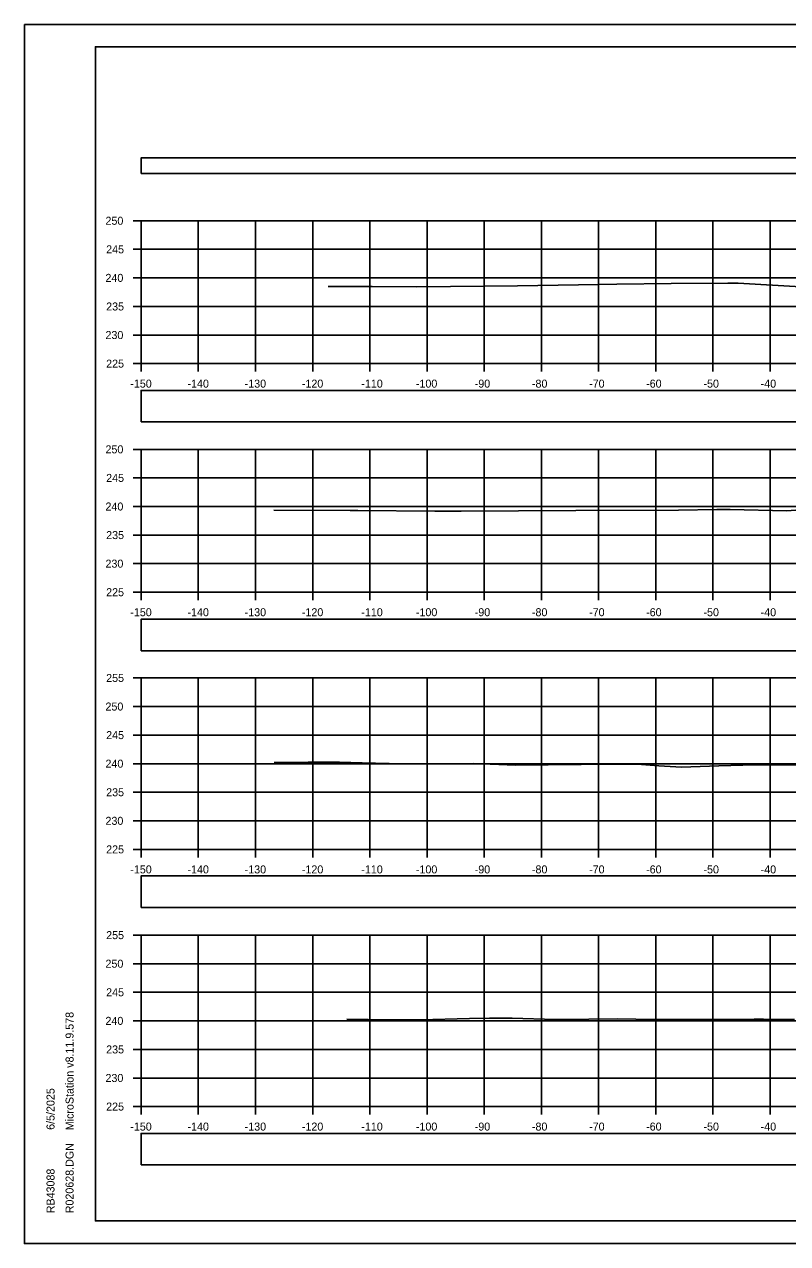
# Model space of a CAD drawing. Extents: x 1369627 to 1374022, y 380035 to 398173.
# Drawn here: x 1370008.8 to 1370142.3, y 380248.2 to 380461.5 of the extents above; entities that cross this region are included whole.
import ezdxf

# ---------------------------------------------------------------- set-up
doc = ezdxf.new("R2010")
doc.units = 0
for name, color, linetype in [('Default', 7, 'Continuous'), ('R_Axis', 7, 'Continuous'), ('R_Axis Annot', 7, 'Continuous'), ('R_Border', 7, 'Continuous'), ('R_Exist Surface', 7, 'Continuous'), ('R_Grid', 7, 'Continuous'), ('R_No Plot', 7, 'Continuous')]:
    doc.layers.add(name, color=color, linetype=linetype)

msp = doc.modelspace()

# ---------------------------------------------------------------- linework, layer by layer
at = {"layer": 'Default'}
for points in [[(1370029.24, 380435.47), (1370329.24, 380435.47), (1370329.24, 380438.18), (1370029.24, 380438.18)], [(1370029.24, 380391.98), (1370329.24, 380391.98), (1370329.24, 380397.5), (1370029.24, 380397.5)], [(1370029.24, 380351.95), (1370329.24, 380351.95), (1370329.24, 380357.47), (1370029.24, 380357.47)], [(1370029.24, 380307.01), (1370329.24, 380307.01), (1370329.24, 380312.54), (1370029.24, 380312.54)], [(1370029.24, 380261.98), (1370329.24, 380261.98), (1370329.24, 380267.5), (1370029.24, 380267.5)]]:
    msp.add_lwpolyline(points, close=True, dxfattribs=at)
at = {"layer": 'R_Axis'}
for p, q in [((1370027.84, 380427.19), (1370029.24, 380427.19)), ((1370029.24, 380402.19), (1370029.24, 380427.19)), ((1370027.84, 380422.19), (1370029.24, 380422.19)), ((1370027.84, 380417.19), (1370029.24, 380417.19)), ((1370027.84, 380412.19), (1370029.24, 380412.19)), ((1370027.84, 380407.19), (1370029.24, 380407.19)), ((1370027.84, 380402.19), (1370029.24, 380402.19)), ((1370029.24, 380402.19), (1370329.24, 380402.19)), ((1370029.24, 380400.79), (1370029.24, 380402.19)), ((1370039.24, 380400.79), (1370039.24, 380402.19)), ((1370049.24, 380400.79), (1370049.24, 380402.19)), ((1370059.24, 380400.79), (1370059.24, 380402.19)), ((1370069.24, 380400.79), (1370069.24, 380402.19)), ((1370079.24, 380400.79), (1370079.24, 380402.19)), ((1370089.24, 380400.79), (1370089.24, 380402.19)), ((1370099.24, 380400.79), (1370099.24, 380402.19)), ((1370109.24, 380400.79), (1370109.24, 380402.19)), ((1370119.24, 380400.79), (1370119.24, 380402.19)), ((1370129.24, 380400.79), (1370129.24, 380402.19)), ((1370139.24, 380400.79), (1370139.24, 380402.19)), ((1370027.84, 380387.19), (1370029.24, 380387.19)), ((1370029.24, 380362.19), (1370029.24, 380387.19)), ((1370027.84, 380382.19), (1370029.24, 380382.19)), ((1370027.84, 380377.19), (1370029.24, 380377.19)), ((1370027.84, 380372.19), (1370029.24, 380372.19)), ((1370027.84, 380367.19), (1370029.24, 380367.19)), ((1370027.84, 380362.19), (1370029.24, 380362.19)), ((1370029.24, 380362.19), (1370329.24, 380362.19)), ((1370029.24, 380360.79), (1370029.24, 380362.19)), ((1370039.24, 380360.79), (1370039.24, 380362.19)), ((1370049.24, 380360.79), (1370049.24, 380362.19)), ((1370059.24, 380360.79), (1370059.24, 380362.19)), ((1370069.24, 380360.79), (1370069.24, 380362.19)), ((1370079.24, 380360.79), (1370079.24, 380362.19)), ((1370089.24, 380360.79), (1370089.24, 380362.19)), ((1370099.24, 380360.79), (1370099.24, 380362.19)), ((1370109.24, 380360.79), (1370109.24, 380362.19)), ((1370119.24, 380360.79), (1370119.24, 380362.19)), ((1370129.24, 380360.79), (1370129.24, 380362.19)), ((1370139.24, 380360.79), (1370139.24, 380362.19)), ((1370027.84, 380347.19), (1370029.24, 380347.19)), ((1370029.24, 380317.19), (1370029.24, 380347.19)), ((1370027.84, 380342.19), (1370029.24, 380342.19)), ((1370027.84, 380337.19), (1370029.24, 380337.19)), ((1370027.84, 380332.19), (1370029.24, 380332.19)), ((1370027.84, 380327.19), (1370029.24, 380327.19)), ((1370027.84, 380322.19), (1370029.24, 380322.19)), ((1370027.84, 380317.19), (1370029.24, 380317.19)), ((1370029.24, 380317.19), (1370329.24, 380317.19)), ((1370029.24, 380315.79), (1370029.24, 380317.19)), ((1370039.24, 380315.79), (1370039.24, 380317.19)), ((1370049.24, 380315.79), (1370049.24, 380317.19)), ((1370059.24, 380315.79), (1370059.24, 380317.19)), ((1370069.24, 380315.79), (1370069.24, 380317.19)), ((1370079.24, 380315.79), (1370079.24, 380317.19)), ((1370089.24, 380315.79), (1370089.24, 380317.19)), ((1370099.24, 380315.79), (1370099.24, 380317.19)), ((1370109.24, 380315.79), (1370109.24, 380317.19)), ((1370119.24, 380315.79), (1370119.24, 380317.19)), ((1370129.24, 380315.79), (1370129.24, 380317.19)), ((1370139.24, 380315.79), (1370139.24, 380317.19)), ((1370027.84, 380302.19), (1370029.24, 380302.19)), ((1370029.24, 380272.19), (1370029.24, 380302.19)), ((1370027.84, 380297.19), (1370029.24, 380297.19)), ((1370027.84, 380292.19), (1370029.24, 380292.19)), ((1370027.84, 380287.19), (1370029.24, 380287.19)), ((1370027.84, 380282.19), (1370029.24, 380282.19)), ((1370027.84, 380277.19), (1370029.24, 380277.19)), ((1370027.84, 380272.19), (1370029.24, 380272.19)), ((1370029.24, 380272.19), (1370329.24, 380272.19)), ((1370029.24, 380270.79), (1370029.24, 380272.19)), ((1370039.24, 380270.79), (1370039.24, 380272.19)), ((1370049.24, 380270.79), (1370049.24, 380272.19)), ((1370059.24, 380270.79), (1370059.24, 380272.19)), ((1370069.24, 380270.79), (1370069.24, 380272.19)), ((1370079.24, 380270.79), (1370079.24, 380272.19)), ((1370089.24, 380270.79), (1370089.24, 380272.19)), ((1370099.24, 380270.79), (1370099.24, 380272.19)), ((1370109.24, 380270.79), (1370109.24, 380272.19)), ((1370119.24, 380270.79), (1370119.24, 380272.19)), ((1370129.24, 380270.79), (1370129.24, 380272.19)), ((1370139.24, 380270.79), (1370139.24, 380272.19))]:
    msp.add_line(p, q, dxfattribs=at)
at = {"layer": 'R_Border'}
for p, q in [((1370021.24, 380457.65), (1370337.42, 380457.65)), ((1370021.24, 380252.19), (1370021.24, 380457.65)), ((1370021.24, 380252.19), (1370021.24, 380252.19)), ((1370337.42, 380252.19), (1370021.24, 380252.19))]:
    msp.add_line(p, q, dxfattribs=at)
at = {"layer": 'R_Exist Surface'}
for points in [[(1370061.95, 380415.71), (1370069.65, 380415.66), (1370077.48, 380415.65), (1370095.04, 380415.82), (1370105.74, 380415.97), (1370112.41, 380416.08), (1370121.92, 380416.2), (1370131.86, 380416.25), (1370133.62, 380416.26), (1370144.62, 380415.62)], [(1370052.47, 380376.57), (1370065.77, 380376.49), (1370067.13, 380376.47), (1370080.63, 380376.39), (1370081.86, 380376.38), (1370085.2, 380376.4), (1370105.24, 380376.48), (1370123.24, 380376.54), (1370129.92, 380376.66), (1370132.25, 380376.65), (1370142.11, 380376.41), (1370143.75, 380376.53)], [(1370052.48, 380332.42), (1370052.81, 380332.41), (1370054.84, 380332.42), (1370058.48, 380332.48), (1370063.92, 380332.47), (1370067.88, 380332.36), (1370074.94, 380332.15), (1370087.39, 380332.22), (1370094.68, 380331.94), (1370106.21, 380332.03), (1370116.01, 380332.12), (1370119.76, 380331.83), (1370123.72, 380331.57), (1370130.26, 380331.81), (1370136.55, 380332), (1370150.24, 380332)], [(1370065.21, 380287.51), (1370072.67, 380287.38), (1370078.07, 380287.37), (1370086.68, 380287.6), (1370090.15, 380287.64), (1370094.13, 380287.64), (1370101.67, 380287.44), (1370107.54, 380287.47), (1370112.53, 380287.53), (1370115.76, 380287.49), (1370126.93, 380287.4), (1370127.96, 380287.45), (1370136.46, 380287.47), (1370138.06, 380287.47), (1370143.52, 380287.41)]]:
    msp.add_lwpolyline(points, dxfattribs=at)
at = {"layer": 'R_Grid'}
for p, q in [((1370029.24, 380427.19), (1370329.24, 380427.19)), ((1370029.24, 380402.19), (1370029.24, 380427.19)), ((1370039.24, 380402.19), (1370039.24, 380427.19)), ((1370049.24, 380402.19), (1370049.24, 380427.19)), ((1370059.24, 380402.19), (1370059.24, 380427.19)), ((1370069.24, 380402.19), (1370069.24, 380427.19)), ((1370079.24, 380402.19), (1370079.24, 380427.19)), ((1370089.24, 380402.19), (1370089.24, 380427.19)), ((1370099.24, 380402.19), (1370099.24, 380427.19)), ((1370109.24, 380402.19), (1370109.24, 380427.19)), ((1370119.24, 380402.19), (1370119.24, 380427.19)), ((1370129.24, 380402.19), (1370129.24, 380427.19)), ((1370139.24, 380402.19), (1370139.24, 380427.19)), ((1370029.24, 380422.19), (1370329.24, 380422.19)), ((1370029.24, 380417.19), (1370329.24, 380417.19)), ((1370029.24, 380412.19), (1370329.24, 380412.19)), ((1370029.24, 380407.19), (1370329.24, 380407.19)), ((1370029.24, 380402.19), (1370329.24, 380402.19)), ((1370029.24, 380387.19), (1370329.24, 380387.19)), ((1370029.24, 380362.19), (1370029.24, 380387.19)), ((1370039.24, 380362.19), (1370039.24, 380387.19)), ((1370049.24, 380362.19), (1370049.24, 380387.19)), ((1370059.24, 380362.19), (1370059.24, 380387.19)), ((1370069.24, 380362.19), (1370069.24, 380387.19)), ((1370079.24, 380362.19), (1370079.24, 380387.19)), ((1370089.24, 380362.19), (1370089.24, 380387.19)), ((1370099.24, 380362.19), (1370099.24, 380387.19)), ((1370109.24, 380362.19), (1370109.24, 380387.19)), ((1370119.24, 380362.19), (1370119.24, 380387.19)), ((1370129.24, 380362.19), (1370129.24, 380387.19)), ((1370139.24, 380362.19), (1370139.24, 380387.19)), ((1370029.24, 380382.19), (1370329.24, 380382.19)), ((1370029.24, 380377.19), (1370329.24, 380377.19)), ((1370029.24, 380372.19), (1370329.24, 380372.19)), ((1370029.24, 380367.19), (1370329.24, 380367.19)), ((1370029.24, 380362.19), (1370329.24, 380362.19)), ((1370029.24, 380347.19), (1370329.24, 380347.19)), ((1370029.24, 380317.19), (1370029.24, 380347.19)), ((1370039.24, 380317.19), (1370039.24, 380347.19)), ((1370049.24, 380317.19), (1370049.24, 380347.19)), ((1370059.24, 380317.19), (1370059.24, 380347.19)), ((1370069.24, 380317.19), (1370069.24, 380347.19)), ((1370079.24, 380317.19), (1370079.24, 380347.19)), ((1370089.24, 380317.19), (1370089.24, 380347.19)), ((1370099.24, 380317.19), (1370099.24, 380347.19)), ((1370109.24, 380317.19), (1370109.24, 380347.19)), ((1370119.24, 380317.19), (1370119.24, 380347.19)), ((1370129.24, 380317.19), (1370129.24, 380347.19)), ((1370139.24, 380317.19), (1370139.24, 380347.19)), ((1370029.24, 380342.19), (1370329.24, 380342.19)), ((1370029.24, 380337.19), (1370329.24, 380337.19)), ((1370029.24, 380332.19), (1370329.24, 380332.19)), ((1370029.24, 380327.19), (1370329.24, 380327.19)), ((1370029.24, 380322.19), (1370329.24, 380322.19)), ((1370029.24, 380317.19), (1370329.24, 380317.19)), ((1370029.24, 380302.19), (1370329.24, 380302.19)), ((1370029.24, 380272.19), (1370029.24, 380302.19)), ((1370039.24, 380272.19), (1370039.24, 380302.19)), ((1370049.24, 380272.19), (1370049.24, 380302.19)), ((1370059.24, 380272.19), (1370059.24, 380302.19)), ((1370069.24, 380272.19), (1370069.24, 380302.19)), ((1370079.24, 380272.19), (1370079.24, 380302.19)), ((1370089.24, 380272.19), (1370089.24, 380302.19)), ((1370099.24, 380272.19), (1370099.24, 380302.19)), ((1370109.24, 380272.19), (1370109.24, 380302.19)), ((1370119.24, 380272.19), (1370119.24, 380302.19)), ((1370129.24, 380272.19), (1370129.24, 380302.19)), ((1370139.24, 380272.19), (1370139.24, 380302.19)), ((1370029.24, 380297.19), (1370329.24, 380297.19)), ((1370029.24, 380292.19), (1370329.24, 380292.19)), ((1370029.24, 380287.19), (1370329.24, 380287.19)), ((1370029.24, 380282.19), (1370329.24, 380282.19)), ((1370029.24, 380277.19), (1370329.24, 380277.19)), ((1370029.24, 380272.19), (1370329.24, 380272.19))]:
    msp.add_line(p, q, dxfattribs=at)
at = {"layer": 'R_No Plot'}
for p, q in [((1370008.84, 380461.55), (1370342.17, 380461.55)), ((1370008.84, 380248.22), (1370342.17, 380248.22))]:
    msp.add_line(p, q, dxfattribs=at)
for points in [[(1370008.83, 380461.55), (1370342.17, 380461.55), (1370342.17, 380248.21), (1370008.83, 380248.21)], [(1370255.16, 380457.65), (1370274.78, 380457.65), (1370274.78, 380447.77), (1370290.89, 380447.77), (1370314.09, 380447.77), (1370314.09, 380415.1), (1370337.3, 380415.1), (1370337.42, 380252.19), (1370021.24, 380252.19), (1370021.24, 380457.65)]]:
    msp.add_lwpolyline(points, close=True, dxfattribs=at)

# ---------------------------------------------------------------- texts
at = {"layer": 'R_Axis Annot'}
for s, p in [('250', (1370023.01, 380426.49)), ('245', (1370023.13, 380421.49)), ('240', (1370023.01, 380416.49)), ('235', (1370023.13, 380411.49)), ('230', (1370023.01, 380406.49)), ('225', (1370023.13, 380401.49)), ('-150', (1370027.35, 380397.99)), ('-140', (1370037.35, 380397.99)), ('-130', (1370047.35, 380397.99)), ('-120', (1370057.35, 380397.99)), ('-110', (1370067.75, 380397.99)), ('-100', (1370077.29, 380397.99)), ('-90', (1370087.58, 380397.99)), ('-80', (1370097.58, 380397.99)), ('-70', (1370107.58, 380397.99)), ('-60', (1370117.55, 380397.99)), ('-50', (1370127.58, 380397.99)), ('-40', (1370137.58, 380397.99)), ('250', (1370023.01, 380386.49)), ('245', (1370023.13, 380381.49)), ('240', (1370023.01, 380376.49)), ('235', (1370023.13, 380371.49)), ('230', (1370023.01, 380366.49)), ('225', (1370023.13, 380361.49)), ('-150', (1370027.35, 380357.99)), ('-140', (1370037.35, 380357.99)), ('-130', (1370047.35, 380357.99)), ('-120', (1370057.35, 380357.99)), ('-110', (1370067.75, 380357.99)), ('-100', (1370077.29, 380357.99)), ('-90', (1370087.58, 380357.99)), ('-80', (1370097.58, 380357.99)), ('-70', (1370107.58, 380357.99)), ('-60', (1370117.55, 380357.99)), ('-50', (1370127.58, 380357.99)), ('-40', (1370137.58, 380357.99)), ('255', (1370023.13, 380346.49)), ('250', (1370023.01, 380341.49)), ('245', (1370023.13, 380336.49)), ('240', (1370023.01, 380331.49)), ('235', (1370023.13, 380326.49)), ('230', (1370023.01, 380321.49)), ('225', (1370023.13, 380316.49)), ('-150', (1370027.35, 380312.99)), ('-140', (1370037.35, 380312.99)), ('-130', (1370047.35, 380312.99)), ('-120', (1370057.35, 380312.99)), ('-110', (1370067.75, 380312.99)), ('-100', (1370077.29, 380312.99)), ('-90', (1370087.58, 380312.99)), ('-80', (1370097.58, 380312.99)), ('-70', (1370107.58, 380312.99)), ('-60', (1370117.55, 380312.99)), ('-50', (1370127.58, 380312.99)), ('-40', (1370137.58, 380312.99)), ('255', (1370023.13, 380301.49)), ('250', (1370023.01, 380296.49)), ('245', (1370023.13, 380291.49)), ('240', (1370023.01, 380286.49)), ('235', (1370023.13, 380281.49)), ('230', (1370023.01, 380276.49)), ('225', (1370023.13, 380271.49)), ('-150', (1370027.35, 380267.99)), ('-140', (1370037.35, 380267.99)), ('-130', (1370047.35, 380267.99)), ('-120', (1370057.35, 380267.99)), ('-110', (1370067.75, 380267.99)), ('-100', (1370077.29, 380267.99)), ('-90', (1370087.58, 380267.99)), ('-80', (1370097.58, 380267.99)), ('-70', (1370107.58, 380267.99)), ('-60', (1370117.55, 380267.99)), ('-50', (1370127.58, 380267.99)), ('-40', (1370137.58, 380267.99))]:
    msp.add_text(s, height=1.4, dxfattribs=at).set_placement(p)
at = {"layer": 'R_Border'}
for s, p in [('MicroStation v8.11.9.578', (1370017.43, 380268.05)), ('6/5/2025', (1370014.1, 380268.12)), ('R020628.DGN', (1370017.43, 380253.52)), ('RB43088', (1370014.1, 380253.52))]:
    msp.add_text(s, height=1.4, rotation=90, dxfattribs=at).set_placement(p)

doc.saveas('drawing.dxf')
